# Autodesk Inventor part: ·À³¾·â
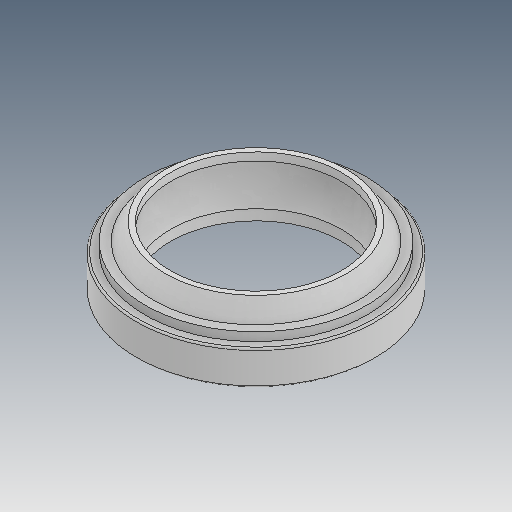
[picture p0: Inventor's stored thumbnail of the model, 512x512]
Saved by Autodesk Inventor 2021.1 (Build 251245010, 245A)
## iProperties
Created: 2014-12
Part Number: ·À³¾·â
Material: Ogólny
Document SubType Name: Modeling
Designer: user
Density: 1 g/cm^3
Appearance: Domyślna
Author: user
Revision Number: ÈÎºÎ
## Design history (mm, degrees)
feature "ÊäÈë1"
node "Bryła1"
